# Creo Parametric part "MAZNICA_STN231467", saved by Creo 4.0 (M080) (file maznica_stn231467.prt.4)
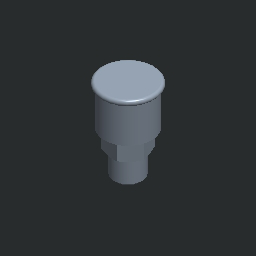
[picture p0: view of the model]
Units: millimeter Kilogram Sec (mmKs); MM, KILOGRAM, SECS
Materials in the file: OCEL_N

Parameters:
  MFG_WP_MATERIAL = "OCEL"
  NAZOV = "MAZNICA_STN231467"
  NORMA = "STN 23 1467"
  PTC_MATERIAL_NAME = "OCEL_N"

Other parameters: HMOTNOST, HUSTOTA, D25, D19, D22

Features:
  1. datum plane "DTM1"
  2. cut
  3. datum plane "DTM4"
  4. protrusion
  5. chamfer
  6. datum plane "DTM5"
  7. datum plane "DTM6"

Other named items: BLIND

Layers: 1, 2, 3, 4, 5, 6, 7, 8, 9, 10, 11, 12, 13, 14, 15, 16, 17, 18, 19, 20, 21, 22, 23, 24, 25, 26, 27, 28, 29, 30, 31, 32

Family table entries: GENERIC, MAZNICA_2, MAZNICA_STN231467, value(d_val), 2/ , 2/3, 2/., 2/(, value(i_val), MAZNICA_4, MAZNICA_STN231467, !/(, 2/", 2/8, 2/., 2/$, 2/,, MAZNICA_12, MAZNICA_STN231467, !/(, 2/$, 2/A, 2/., 2/&, 2/1, MAZNICA_22, MAZNICA_STN231467, !/(, 2/&, 2/E, 2/., 2/(, 2/1, MAZNICA_42, MAZNICA_STN231467, !/(, 2/&, 2/., 2/(, 2/1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

Surfaces: 11 plane, 6 cylinder, 6 cone, 2 torus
